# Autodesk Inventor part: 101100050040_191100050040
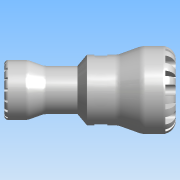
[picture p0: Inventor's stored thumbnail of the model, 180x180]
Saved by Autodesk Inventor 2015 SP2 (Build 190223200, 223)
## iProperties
Created: 2016-12
Part Number: 101100050040_191100050040
Material: PVC-Piping
Description: PLASSON REDUCING COUPLING 50X40 SERIES 1
Document SubType Name: Modeling
Designer: KIM
Mass: 113.204 g
Surface Area: 237.851 cm^2
Volume: 80.8599 cm^3
Density: 1.4 g/cm^3
Appearance: Smooth - White
Author: KIM
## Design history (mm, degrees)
derived "1011.ipt"
feature "Solid1::1011.ipt"
tag "TaggingFeature1"
body "Solid1"
other parameters: "d0" = 165, "d2" = 32.34, "d4" = 85, "d6" = 77, "d7" = 4.16667, "d8" = 58, "d11" = 22.26, "d12" = 53, "d13" = 3.33333, "d14" = 68, "d15" = 46.4, "d16" = 20 deg, "d17" = 20 deg, "d18" = 130 deg, "d26" = 0, "d28" = 360 deg, "d30" = 8 deg, "d31" = 1, "d32" = 8 deg, "d33" = 1, "d35" = 0, "d37" = 360 deg, "d39" = 3.2, "d42" = 3.2, "d43" = 0, "d45" = 360 deg, "d47" = 0.8, "d48" = 8 deg, "d49" = 8 deg, "d50" = 0.8, "d52" = 0, "d54" = 360 deg, "d56" = 11.6, "d57" = 17, "d58" = 0.5, "d60" = 10.2, "d61" = 12.5, "d62" = 16.2, "d63" = 0, "d66" = 0, "d68" = 360 deg, "d75" = 13.25673, "d77" = 66.3, "d78" = 0.85, "E_" = 85, "H_" = 165, "l_" = 77, "E1" = 58, "l1" = 53, "Plasson" = 1, "d20" = 4, "d21" = 12.5, "d23" = 85, "d40" = 58, "d59" = 26.51345
